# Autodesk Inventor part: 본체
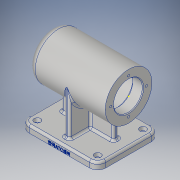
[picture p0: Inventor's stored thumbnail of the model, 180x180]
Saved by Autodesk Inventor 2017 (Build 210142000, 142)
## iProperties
Part Number: 본체
Material: 알루미늄 6061
Document SubType Name: Modeling
Designer: 7-1
Density: 2.7 g/cm^3
Appearance: 알루미늄 - 평지
Mass: 1024.73 g
Surface Area: 758.632 cm^2
Volume: 379.531 cm^3
Author: 7-1
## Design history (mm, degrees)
sketch "스케치1"
  geometry: L1 (0, 0)-(-112, 0); L2 (0, 21)-(0, 34); L3 (-112, 0)-(-112, 24); L4 (-102, 34)-(0, 34); L5 (-106, 0)-(-106, 10.5); L6 (-106, 10.5)-(-103, 10.5); L7 (-103, 10.5)-(-103, 15.7); L8 (-102.7, 16)-(-99, 16); L9 (-99, 16)-(-99, 17.2); L10 (-98.7, 17.5)-(-81, 17.5); L11 (-69, 24)-(-15, 24); L12 (-15, 24)-(-15, 21); L13 (-69, 24)-(-69, 21); L14 (-69, 21)-(-80.7, 21); L15 (-81, 20.7)-(-81, 17.5); L16 (-15, 21)-(0, 21); L17 (0, 34)-(0, 0); L18 (-112, 0)-(-106, 0); L19 (0, 34)-(0, 21); A1 r 0.3 centre (-102.7, 15.7) between (-102.7, 16) and (-103, 15.7); A2 r 0.3 centre (-98.7, 17.2) between (-98.7, 17.5) and (-99, 17.2); A3 r 0.3 centre (-80.7, 20.7) between (-80.7, 21) and (-81, 20.7); A4 r 10 centre (-102, 24) between (-102, 34) and (-112, 24)
  constraints: 38 end point, 13 perpendicular, 8 point on circle, 8 tangent, 4 centre point, 3 vertical, 2 equal radius, 1 collinear, 1 horizontal, 1 point on line
  dimensions: "d1" = 112 distance between parallel lines of L2 L3; "d2" = 21 diameter of L6 L1; "d3" = 32 diameter of L8 L1; "d4" = 35 diameter of L10 L1; "d5" = 42 diameter of L14 L1; "d6" = 48 diameter of L11 L1; "d7" = 68 diameter of L4 L1; "d8" = 42 diameter of L16 L1; "d9" = 15 distance between parallel lines of L2 L12; "d10" = 54 distance between parallel lines of L12 L13; "d11" = 12 distance between parallel lines of L13 L15; "d12" = 18 distance between parallel lines of L15 L9; "d13" = 3 distance between parallel lines of L7 L5; "d14" = 4 distance between parallel lines of L9 L7; "d15" = 0.3 radius of A1; "d16" = 10 radius of A4
revolve "회전1" sketch "스케치1" stored, may be unused: angle "d17" = 90 deg
sketch "스케치2"
  geometry: 1 further point
node "작업 평면1"
sketch "스케치3"
  geometry: L1 (100, -45)-(12, -45); L2 (0, -33)-(0, 33); L3 (12, 45)-(100, 45); L4 (112, 33)-(112, -33); A1 r 12 centre (100, -33) between (100, -45) and (112, -33); A2 r 12 centre (100, 33) between (112, 33) and (100, 45); A3 r 12 centre (12, 33) between (12, 45) and (0, 33); A4 r 12 centre (12, -33) between (0, -33) and (12, -45); 4 further points
  constraints: 8 end point, 8 point on circle, 8 tangent, 6 point on line, 4 centre point, 3 equal radius, 2 parallel, 1 horizontal, 1 perpendicular
  dimensions: "d19" = 112 distance of point (0, 45) point (112, 45); "d20" = 90 distance of point (0, -45) point (0, 45); "d21" = 0 distance from line of point (0, 0) L2; "d22" = 45 distance from line of point (0, 0) L3; "d23" = 12 radius of A1
extrude "돌출1" join sketch "스케치3" distance "d24" = 10; taper "d25" = 0 deg
sketch "스케치4"
  geometry: A1 r 12 centre (-100, 33) between (-100, 45) and (-112, 33) reference; A2 r 12 centre (-100, -33) between (-112, -33) and (-100, -45) reference; A3 r 12 centre (-12, -33) between (-12, -45) and (0, -33) reference; A4 r 12 centre (-12, 33) between (0, 33) and (-12, 45) reference; 5 further points
  constraints: 4 coincident
hole "구멍1" sketch "스케치4" at (-100, -33), (-12, -33), (-100, 33), (-12, 33) diameter "d26" = 5.5; stored, may be unused: countersink angle "d30" = 82 deg, drill point angle "d32" = 0 deg; dims "d27" = 6, "d28" = 9.5, "d29" = 5.4, "d31" = 10
sketch "스케치5"
  geometry: L1 (-112, -33)-(-112, 33) reference; L2 (-94, 4)-(-94, 0); L3 (-18, 4)-(-18, 0); L4 (-12, -45)-(-100, -45) reference; L5 (0, 0)-(-112, 0); L6 (-56, 0)-(-56, 34); L7 (-60, 4)-(-60, 34); L8 (-52, 4)-(-52, 34); L9 (-60, 34)-(-52, 34); L10 (-18, 4)-(-52, 4); L11 (-60, 4)-(-94, 4); L12 (0, 33)-(0, -33) reference; L13 (-52, -4)-(-52, -34); L14 (-60, -34)-(-52, -34); L15 (-60, -4)-(-60, -34); L16 (-60, -4)-(-94, -4); L17 (-94, -4)-(-94, 0); L18 (-18, -4)-(-52, -4); L19 (-18, -4)-(-18, 0)
  constraints: 32 end point, 6 symmetric about line, 3 vertical, 2 midpoint, 2 parallel, 1 horizontal, 1 point on line
  dimensions: "d42" = 76 distance of L3.start L2.start; "d43" = 76 distance of L3.end L2.end; "d47" = 4 distance between parallel lines of L6 L7; "d48" = 4 distance between parallel lines of L6 L8; "d49" = 68 diameter of L9 L5; "d50" = 8 diameter of L10 L5; "d53" = 8 diameter of L11 L5; "d54" = 94 distance between parallel lines of L12 L2
extrude "돌출2" join sketch "스케치5" stored distance "d55" = 10; taper "d56" = 0 deg
sketch "스케치6" dims "d57" = 52
  geometry: 6 further points
  constraints: 2 vertical alignment, 1 coincident, 7 other
  dimensions: "d60" = 360 deg dimension on point (0, 0) point (0, 26) (derived)
hole "구멍2" sketch "스케치6" at (0, -26), (-26, 0), (0, 26), (26, 0) diameter "d62" = 3.242; stored, may be unused: countersink angle "d66" = 90 deg, drill point angle "d68" = 118 deg; dims "d63" = 8, "d64" = 4, "d65" = 2, "d67" = 11
sketch "스케치7"
  geometry: L1 (100, 0)-(100, 10) reference; 2 further points
  constraints: 1 other
  dimensions: "d69" = 56 distance from line of L1 point (44, 3); "d70" = 3 vertical distance of L1.start point (44, 3)
feature "엠보싱1" sketch "스케치7" dims "d1" = 112, "d2" = 21, "d3" = 32, "d4" = 35, "d5" = 42, "d6" = 48, "d7" = 68, "d8" = 42, "d9" = 15, "d10" = 54, "d11" = 12, "d12" = 18, "d13" = 3, "d14" = 4, "d15" = 0.3, "d16" = 10, "d71" = 0.5, "d72" = 0
fillet "모깎기1" dims "d73" = 3
fillet "모깎기2" dims "d74" = 3
fillet "모깎기3" dims "d75" = 3
chamfer "모따기1" distance "d76" = 1; stored, may be unused: second distance "d77" = 2, angle "d78" = 45 deg
fillet "모깎기5" dims "d80" = 3
fillet "모깎기6" dims "d81" = 3
node "솔리드1"
other parameters: "d18" = -74
